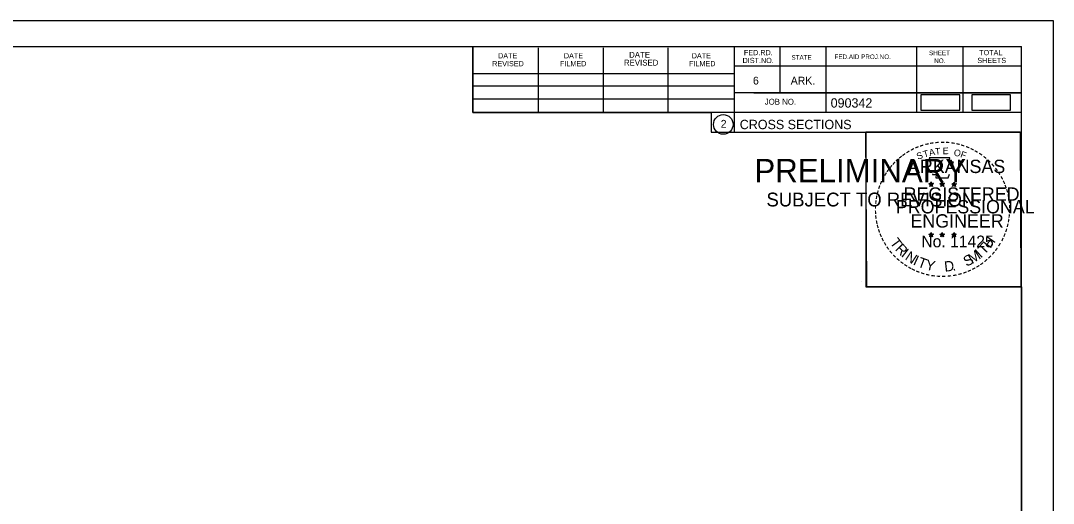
# Model space of a CAD drawing. Extents: x 1370515 to 1370849, y 383299 to 386073.
# Drawn here: x 1370694 to 1370848.7, y 386000.4 to 386072.8 of the extents above; entities that cross this region are included whole.
import ezdxf

# ---------------------------------------------------------------- set-up
doc = ezdxf.new("R2010")
doc.units = 0
for name, color, linetype in [('R_Border', 7, 'Continuous'), ('R_Border PE', 7, 'Continuous'), ('R_Border Prem', 7, 'Continuous'), ('R_Detour', 7, 'Continuous'), ('R_No Plot', 7, 'Continuous')]:
    doc.layers.add(name, color=color, linetype=linetype)

msp = doc.modelspace()

# ---------------------------------------------------------------- linework, layer by layer
at = {"layer": 'R_Border'}
for p, q in [((1370527.8, 386068.92), (1370843.98, 386068.92)), ((1370761.72, 386059.04), (1370761.72, 386068.92)), ((1370771.58, 386059.04), (1370771.58, 386068.72)), ((1370781.34, 386059.04), (1370781.34, 386068.72)), ((1370791.02, 386059.04), (1370791.02, 386068.72)), ((1370800.88, 386068.92), (1370800.88, 386056.12)), ((1370807.72, 386068.92), (1370807.72, 386061.98)), ((1370814.66, 386068.92), (1370814.66, 386059.04)), ((1370828.24, 386068.92), (1370828.24, 386059.04)), ((1370835.18, 386068.92), (1370835.18, 386059.04)), ((1370843.98, 385863.46), (1370843.98, 386068.92)), ((1370843.98, 386065.98), (1370800.88, 386065.98)), ((1370843.98, 386066), (1370843.98, 386066)), ((1370761.72, 386064.9), (1370800.88, 386064.9)), ((1370761.72, 386063.04), (1370800.88, 386063.04)), ((1370761.72, 386059.04), (1370761.72, 386061.1)), ((1370761.72, 386061.1), (1370800.88, 386061.1)), ((1370843.98, 386061.98), (1370800.88, 386061.98)), ((1370803.84, 386061.98), (1370843.98, 386061.98)), ((1370843.98, 386059.04), (1370761.72, 386059.04)), ((1370800.88, 386056.12), (1370843.98, 386056.12))]:
    msp.add_line(p, q, dxfattribs=at)
msp.add_circle((1370799.27, 386057.26), 1.47, dxfattribs=at)
at = {"layer": 'R_Border PE'}
for p, q in [((1370830.07, 386048.38), (1370830.42, 386048.27)), ((1370830.07, 386048.38), (1370830.32, 386048.33)), ((1370830.07, 386048.38), (1370830.3, 386048.26)), ((1370830.42, 386048.63), (1370830.37, 386048.38)), ((1370830.42, 386048.27), (1370830.42, 386048.63)), ((1370830.42, 386048.63), (1370830.46, 386048.38)), ((1370830.76, 386048.38), (1370830.42, 386048.27)), ((1370830.76, 386048.38), (1370830.48, 386048.33)), ((1370830.76, 386048.38), (1370830.56, 386048.28)), ((1370831.74, 386048.38), (1370832.09, 386048.27)), ((1370831.74, 386048.38), (1370831.99, 386048.33)), ((1370831.74, 386048.38), (1370831.97, 386048.26)), ((1370832.09, 386048.63), (1370832.04, 386048.38)), ((1370832.09, 386048.27), (1370832.09, 386048.63)), ((1370832.09, 386048.63), (1370832.13, 386048.38)), ((1370832.43, 386048.38), (1370832.09, 386048.27)), ((1370832.43, 386048.38), (1370832.15, 386048.33)), ((1370832.43, 386048.38), (1370832.23, 386048.28)), ((1370833.5, 386048.37), (1370833.85, 386048.26)), ((1370833.5, 386048.37), (1370833.75, 386048.32)), ((1370833.5, 386048.37), (1370833.74, 386048.25)), ((1370833.85, 386048.62), (1370833.81, 386048.37)), ((1370833.85, 386048.26), (1370833.85, 386048.62)), ((1370833.85, 386048.62), (1370833.9, 386048.37)), ((1370834.2, 386048.37), (1370833.85, 386048.26)), ((1370834.2, 386048.37), (1370833.91, 386048.32)), ((1370834.2, 386048.37), (1370833.99, 386048.27)), ((1370830.2, 386047.97), (1370830.42, 386048.27)), ((1370830.2, 386047.97), (1370830.33, 386048.22)), ((1370830.2, 386047.97), (1370830.41, 386048.19)), ((1370830.63, 386047.97), (1370830.41, 386048.19)), ((1370830.63, 386047.97), (1370830.42, 386048.27)), ((1370830.63, 386047.97), (1370830.49, 386048.26)), ((1370831.87, 386047.97), (1370832.09, 386048.27)), ((1370831.87, 386047.97), (1370832, 386048.22)), ((1370831.87, 386047.97), (1370832.08, 386048.19)), ((1370832.3, 386047.97), (1370832.08, 386048.19)), ((1370832.3, 386047.97), (1370832.09, 386048.27)), ((1370832.3, 386047.97), (1370832.16, 386048.26)), ((1370833.63, 386047.96), (1370833.85, 386048.26)), ((1370833.63, 386047.96), (1370833.76, 386048.2)), ((1370833.63, 386047.96), (1370833.85, 386048.18)), ((1370834.06, 386047.96), (1370833.85, 386048.26)), ((1370834.06, 386047.96), (1370833.85, 386048.17)), ((1370834.06, 386047.96), (1370833.93, 386048.25)), ((1370830.06, 386040.81), (1370830.41, 386040.7)), ((1370830.06, 386040.81), (1370830.32, 386040.76)), ((1370830.06, 386040.81), (1370830.3, 386040.68)), ((1370830.2, 386040.4), (1370830.41, 386040.7)), ((1370830.2, 386040.4), (1370830.32, 386040.64)), ((1370830.2, 386040.4), (1370830.41, 386040.62)), ((1370830.41, 386041.06), (1370830.37, 386040.81)), ((1370830.41, 386040.7), (1370830.41, 386041.06)), ((1370830.41, 386041.06), (1370830.46, 386040.81)), ((1370830.76, 386040.81), (1370830.41, 386040.7)), ((1370830.62, 386040.4), (1370830.41, 386040.7)), ((1370830.62, 386040.4), (1370830.41, 386040.61)), ((1370830.76, 386040.81), (1370830.47, 386040.76)), ((1370830.62, 386040.4), (1370830.49, 386040.69)), ((1370830.76, 386040.81), (1370830.55, 386040.7)), ((1370831.73, 386040.81), (1370832.08, 386040.7)), ((1370831.73, 386040.81), (1370831.98, 386040.76)), ((1370831.73, 386040.81), (1370831.97, 386040.68)), ((1370831.86, 386040.4), (1370832.08, 386040.7)), ((1370831.86, 386040.4), (1370831.99, 386040.64)), ((1370831.86, 386040.4), (1370832.08, 386040.62)), ((1370832.08, 386041.06), (1370832.04, 386040.81)), ((1370832.08, 386040.7), (1370832.08, 386041.06)), ((1370832.08, 386041.06), (1370832.13, 386040.81)), ((1370832.43, 386040.81), (1370832.08, 386040.7)), ((1370832.29, 386040.4), (1370832.08, 386040.7)), ((1370832.29, 386040.4), (1370832.08, 386040.61)), ((1370832.43, 386040.81), (1370832.14, 386040.76)), ((1370832.29, 386040.4), (1370832.16, 386040.69)), ((1370832.43, 386040.81), (1370832.22, 386040.7)), ((1370833.5, 386040.8), (1370833.85, 386040.69)), ((1370833.5, 386040.8), (1370833.75, 386040.75)), ((1370833.5, 386040.8), (1370833.74, 386040.67)), ((1370833.63, 386040.39), (1370833.85, 386040.69)), ((1370833.63, 386040.39), (1370833.76, 386040.63)), ((1370833.85, 386041.05), (1370833.81, 386040.8)), ((1370833.85, 386040.69), (1370833.85, 386041.05)), ((1370833.85, 386041.05), (1370833.9, 386040.8)), ((1370834.19, 386040.8), (1370833.85, 386040.69)), ((1370834.06, 386040.39), (1370833.85, 386040.69)), ((1370834.19, 386040.8), (1370833.91, 386040.75)), ((1370834.06, 386040.39), (1370833.92, 386040.68)), ((1370834.19, 386040.8), (1370833.99, 386040.69)), ((1370833.63, 386040.39), (1370833.85, 386040.61)), ((1370834.06, 386040.39), (1370833.85, 386040.6))]:
    msp.add_line(p, q, dxfattribs=at)
for points in [[(1370830.11, 386052.26), (1370830.38, 386051.43)], [(1370833.62, 386051.34), (1370833.76, 386051.62), (1370833.08, 386051.6), (1370833.22, 386052.26), (1370830.11, 386052.26)], [(1370830.42, 386048.63), (1370830.63, 386047.97), (1370830.07, 386048.38), (1370830.76, 386048.38), (1370830.2, 386047.97), (1370830.42, 386048.63)], [(1370830.6, 386049.83), (1370830.6, 386049.75), (1370831.16, 386049.73), (1370831.11, 386049.26), (1370832.98, 386049.26), (1370833.18, 386049.79)], [(1370832.09, 386048.63), (1370832.3, 386047.97), (1370831.74, 386048.38), (1370832.43, 386048.38), (1370831.87, 386047.97), (1370832.09, 386048.63)], [(1370833.85, 386048.62), (1370834.06, 386047.96), (1370833.5, 386048.37), (1370834.2, 386048.37), (1370833.63, 386047.96), (1370833.85, 386048.62)], [(1370830.41, 386041.06), (1370830.62, 386040.4), (1370830.06, 386040.81), (1370830.76, 386040.81), (1370830.2, 386040.4), (1370830.41, 386041.06)], [(1370832.08, 386041.06), (1370832.29, 386040.4), (1370831.73, 386040.81), (1370832.43, 386040.81), (1370831.86, 386040.4), (1370832.08, 386041.06)], [(1370833.85, 386041.05), (1370834.06, 386040.39), (1370833.5, 386040.8), (1370834.19, 386040.8), (1370833.63, 386040.39), (1370833.85, 386041.05)]]:
    msp.add_lwpolyline(points, dxfattribs=at)
for centre, radius in [((1370830.41, 386048.27), 0.172), ((1370830.41, 386048.27), 0.145), ((1370830.41, 386048.27), 0.116), ((1370830.41, 386048.27), 0.0991), ((1370832.08, 386048.27), 0.172), ((1370832.08, 386048.27), 0.145), ((1370832.08, 386048.27), 0.116), ((1370832.08, 386048.27), 0.0991), ((1370833.85, 386048.26), 0.172), ((1370833.85, 386048.26), 0.145), ((1370833.85, 386048.26), 0.116), ((1370833.85, 386048.26), 0.0991), ((1370830.41, 386048.27), 0.0747), ((1370830.41, 386048.27), 0.0495), ((1370830.41, 386048.27), 0.0296), ((1370832.08, 386048.27), 0.0747), ((1370832.08, 386048.27), 0.0495), ((1370832.08, 386048.27), 0.0296), ((1370833.85, 386048.26), 0.0747), ((1370833.85, 386048.26), 0.0495), ((1370833.85, 386048.26), 0.0296), ((1370830.41, 386040.7), 0.172), ((1370830.41, 386040.7), 0.145), ((1370830.41, 386040.7), 0.116), ((1370830.41, 386040.7), 0.0991), ((1370830.41, 386040.7), 0.0747), ((1370830.41, 386040.7), 0.0495), ((1370830.41, 386040.7), 0.0296), ((1370832.08, 386040.7), 0.172), ((1370832.08, 386040.7), 0.145), ((1370832.08, 386040.7), 0.116), ((1370832.08, 386040.7), 0.0991), ((1370832.08, 386040.7), 0.0747), ((1370832.08, 386040.7), 0.0495), ((1370832.08, 386040.7), 0.0296), ((1370833.85, 386040.69), 0.172), ((1370833.85, 386040.69), 0.145), ((1370833.85, 386040.69), 0.116), ((1370833.85, 386040.69), 0.0991), ((1370833.85, 386040.69), 0.0747), ((1370833.85, 386040.69), 0.0495), ((1370833.85, 386040.69), 0.0296)]:
    msp.add_circle(centre, radius, dxfattribs=at)
at = {"layer": 'R_Detour'}
for points in [[(1370828.87, 386059.39), (1370834.7, 386059.39), (1370834.7, 386061.7), (1370828.87, 386061.7)], [(1370836.5, 386059.39), (1370842.33, 386059.39), (1370842.33, 386061.7), (1370836.5, 386061.7)]]:
    msp.add_lwpolyline(points, close=True, dxfattribs=at)
at = {"layer": 'R_No Plot'}
for p, q in [((1370515.4, 386072.82), (1370848.73, 386072.82)), ((1370820.02, 386033.67), (1370820.02, 386033.67))]:
    msp.add_line(p, q, dxfattribs=at)
for points in [[(1370515.39, 386072.82), (1370848.73, 386072.82), (1370848.73, 385859.48), (1370515.39, 385859.48)], [(1370761.72, 386068.92), (1370761.72, 386059.04), (1370797.45, 386059.04), (1370797.45, 386056.12), (1370820.65, 386056.12), (1370820.65, 386032.91), (1370843.98, 386032.91), (1370843.98, 385863.46), (1370527.8, 385863.46), (1370527.8, 386068.92)], [(1370820.65, 386056.16), (1370843.75, 386056.16), (1370843.87, 386032.91), (1370820.77, 386032.91)]]:
    msp.add_lwpolyline(points, close=True, dxfattribs=at)

# ---------------------------------------------------------------- texts
at = {"layer": 'R_Border'}
for s, height, p in [('DATE', 0.782, (1370765.52, 386067.16)), ('DATE', 0.782, (1370775.38, 386067.16)), ('REVISED', 0.879, (1370784.38, 386066.08)), ('DATE', 0.879, (1370785.16, 386067.26)), ('DATE', 0.782, (1370794.54, 386067.16)), ('DIST.NO.', 0.782, (1370802.16, 386066.46)), ('FED.RD.', 0.782, (1370802.36, 386067.64)), ('STATE', 0.684, (1370809.48, 386066.96)), ('FED.AID PROJ.NO.', 0.684, (1370815.94, 386067.06)), ('SHEET', 0.684, (1370830.1, 386067.64)), ('NO.', 0.684, (1370830.88, 386066.46)), ('SHEETS', 0.782, (1370837.34, 386066.46)), ('TOTAL', 0.782, (1370837.62, 386067.64)), ('REVISED', 0.782, (1370764.64, 386065.98)), ('FILMED', 0.782, (1370774.8, 386065.98)), ('FILMED', 0.782, (1370794.14, 386065.98)), ('6', 1.17, (1370803.72, 386063.24)), ('ARK.', 1.172, (1370809.38, 386063.24)), ('JOB NO.', 0.879, (1370805.48, 386060.22)), ('090342', 1.4, (1370815.36, 386059.78)), ('2', 1.17, (1370798.89, 386056.77)), ('CROSS SECTIONS', 1.4, (1370801.74, 386056.55))]:
    msp.add_text(s, height=height, rotation=360, dxfattribs=at).set_placement(p)
at = {"layer": 'R_Border PE'}
for s, height, rotation, p in [('-', 1.6, 10.2193, (1370830.28, 386053.79)), ('-', 1.6, 5.8968, (1370831.01, 386053.9)), ('-', 1.6, 0.1862, (1370831.78, 386053.97)), ('-', 1.6, 357.743, (1370832.51, 386053.96)), ('-', 1.6, 352.1617, (1370833.25, 386053.9)), ('-', 1.6, 34.0636, (1370826.99, 386052.43)), ('-', 1.6, 28.7918, (1370827.59, 386052.8)), ('-', 1.6, 24.3072, (1370828.22, 386053.12)), ('S', 1, 21.594, (1370828.46, 386051.94)), ('-', 1.6, 19.1761, (1370828.86, 386053.38)), ('T', 1, 16.4036, (1370829.38, 386052.27)), ('-', 1.6, 13.6301, (1370829.61, 386053.63)), ('A', 1, 11.2132, (1370830.2, 386052.52)), ('T', 1, 6.0228, (1370831.05, 386052.68)), ('E', 1, 0.8323, (1370832.16, 386052.79)), ('O', 1, 350.4515, (1370833.76, 386052.58)), ('-', 1.6, 347.2049, (1370833.97, 386053.79)), ('F', 1, 340.0707, (1370834.71, 386052.36)), ('-', 1.6, 342.3362, (1370834.61, 386053.63)), ('-', 1.6, 337.8551, (1370835.34, 386053.41)), ('-', 1.6, 334.1211, (1370835.97, 386053.14)), ('-', 1.6, 329.6409, (1370836.55, 386052.85)), ('-', 1.6, 325.8627, (1370837.19, 386052.49)), ('-', 1.6, 48.423, (1370825.06, 386050.76)), ('-', 1.6, 42.9622, (1370825.5, 386051.24)), ('-', 1.6, 38.9507, (1370825.94, 386051.66)), ('-', 1.6, 36.2317, (1370826.41, 386052.03)), ('ARKANSAS', 2, 360, (1370826.96, 386049.97)), ('-', 1.6, 320.5297, (1370837.8, 386052.07)), ('-', 1.6, 315.5786, (1370838.4, 386051.58)), ('-', 1.6, 58.0706, (1370823.92, 386049.18)), ('-', 1.6, 54.2325, (1370824.24, 386049.71)), ('-', 1.6, 50.6142, (1370824.65, 386050.27)), ('-', 1.6, 309.8797, (1370838.97, 386051.03)), ('-', 1.6, 306.6522, (1370839.5, 386050.43)), ('-', 1.4, 303.6753, (1370839.98, 386049.86)), ('-', 1.6, 67.7743, (1370823.34, 386047.96)), ('-', 1.6, 62.8713, (1370823.6, 386048.57)), ('-', 1.6, 299.6684, (1370840.3, 386049.25)), ('-', 1.6, 294.6628, (1370840.63, 386048.64)), ('-', 1.6, 75.461, (1370822.93, 386046.61)), ('-', 1.6, 72.3945, (1370823.12, 386047.33)), ('REGISTERED', 2, 360, (1370826.28, 386045.82)), ('DWB', 0.01, 360, (1370830.4, 386048.26)), ('DWB', 0.01, 360, (1370832.07, 386048.26)), ('DWB', 0.01, 360, (1370833.84, 386048.25)), ('-', 1.6, 290.5728, (1370840.88, 386048.06)), ('-', 1.6, 285.1233, (1370841.12, 386047.48)), ('-', 1.6, 85.1863, (1370822.72, 386045.21)), ('-', 1.6, 81.2013, (1370822.8, 386045.9)), ('PROFESSIONAL', 2, 360, (1370825.13, 386043.92)), ('-', 1.6, 280.5493, (1370841.32, 386046.74)), ('-', 1.6, 276.5962, (1370841.48, 386045.97)), ('-', 1.6, 94.1959, (1370822.73, 386043.78)), ('-', 1.6, 89.0622, (1370822.69, 386044.51)), ('ENGINEER', 2, 360, (1370827.32, 386041.79)), ('-', 1.6, 263.5172, (1370841.55, 386043.95)), ('-', 1.6, 274.3301, (1370841.54, 386045.25)), ('-', 1.6, 269.9407, (1370841.57, 386044.62)), ('-', 1.6, 98.9479, (1370822.8, 386043.11)), ('-', 1.6, 101.7149, (1370822.94, 386042.38)), ('-', 1.6, 105.4578, (1370823.1, 386041.79)), ('-', 1.6, 255.7626, (1370841.37, 386042.62)), ('-', 1.6, 260.9953, (1370841.48, 386043.3)), ('-', 1.6, 109.0874, (1370823.31, 386041.16)), ('-', 1.6, 114.0643, (1370823.57, 386040.56)), ('No. 11425', 1.757, 360, (1370828.95, 386038.84)), ('DWB', 0.01, 360, (1370830.4, 386040.69)), ('DWB', 0.01, 360, (1370832.07, 386040.69)), ('DWB', 0.01, 360, (1370833.83, 386040.68)), ('-', 1.6, 247.8887, (1370840.97, 386041.23)), ('-', 1.6, 252.8681, (1370841.19, 386041.9)), ('-', 1.6, 115.7288, (1370823.87, 386039.94)), ('-', 1.6, 120.4471, (1370824.23, 386039.36)), ('T', 1.54, 306.0406, (1370824.17, 386039.53)), ('R', 1.54, 314.005, (1370824.93, 386038.49)), ('T', 1.54, 46.6444, (1370838.4, 386037.63)), ('H', 1.54, 54.6088, (1370839.29, 386038.57)), ('-', 1.6, 239.0712, (1370840.31, 386039.85)), ('-', 1.6, 244.6197, (1370840.71, 386040.6)), ('-', 1.6, 125.8934, (1370824.63, 386038.79)), ('-', 1.6, 130.7181, (1370825.09, 386038.24)), ('-', 1.6, 134.2238, (1370825.61, 386037.7)), ('I', 1.54, 321.9694, (1370825.83, 386037.55)), ('N', 1.54, 326.5002, (1370826.4, 386037.08)), ('I', 1.54, 335.3603, (1370827.61, 386036.3)), ('S', 1.54, 26.9312, (1370835.72, 386035.9)), ('M', 1.54, 32.6563, (1370836.56, 386036.3)), ('I', 1.54, 42.1136, (1370837.84, 386037.15)), ('-', 1.6, 225.7653, (1370839, 386038.06)), ('-', 1.6, 231.2538, (1370839.48, 386038.63)), ('-', 1.6, 233.8452, (1370839.91, 386039.19)), ('-', 1.6, 138.9338, (1370826.14, 386037.23)), ('-', 1.6, 144.6463, (1370826.69, 386036.83)), ('-', 1.6, 148.0898, (1370827.25, 386036.46)), ('T', 1.54, 339.8912, (1370828.27, 386035.97)), ('Y', 1.54, 347.8556, (1370829.49, 386035.52)), ('D', 1.54, 6.3969, (1370832.47, 386035.17)), ('-', 1.6, 212.2491, (1370837.4, 386036.7)), ('-', 1.6, 215.7363, (1370837.93, 386037.08)), ('-', 1.6, 221.0851, (1370838.48, 386037.56)), ('-', 1.6, 151.5704, (1370827.83, 386036.13)), ('-', 1.6, 154.6002, (1370828.35, 386035.88)), ('-', 1.6, 158.5612, (1370828.98, 386035.63)), ('-', 1.6, 162.7983, (1370829.67, 386035.42)), ('-', 1.6, 167.5555, (1370830.38, 386035.25)), ('-', 1.6, 173.1155, (1370831.15, 386035.14)), ('-', 1.6, 176.5183, (1370831.9, 386035.09)), ('-', 1.6, 181.5918, (1370832.64, 386035.11)), ('-', 1.6, 185.8167, (1370833.45, 386035.19)), ('-', 1.6, 191.2858, (1370834.19, 386035.32)), ('.', 1.54, 13.7642, (1370833.66, 386035.29)), ('-', 1.6, 195.4743, (1370834.92, 386035.52)), ('-', 1.6, 200.7184, (1370835.6, 386035.76)), ('-', 1.6, 204.2516, (1370836.21, 386036.03)), ('-', 1.6, 207.3568, (1370836.84, 386036.35))]:
    msp.add_text(s, height=height, rotation=rotation, dxfattribs=at).set_placement(p)
at = {"layer": 'R_Border Prem'}
for s, height, p in [('PRELIMINARY', 3.5, (1370803.93, 386048.59)), ('DWB', 0.01, (1370804.68, 386050.44)), ('SUBJECT TO REVISION', 2.0751, (1370805.74, 386044.96))]:
    msp.add_text(s, height=height, rotation=360, dxfattribs=at).set_placement(p)

doc.saveas('drawing.dxf')
